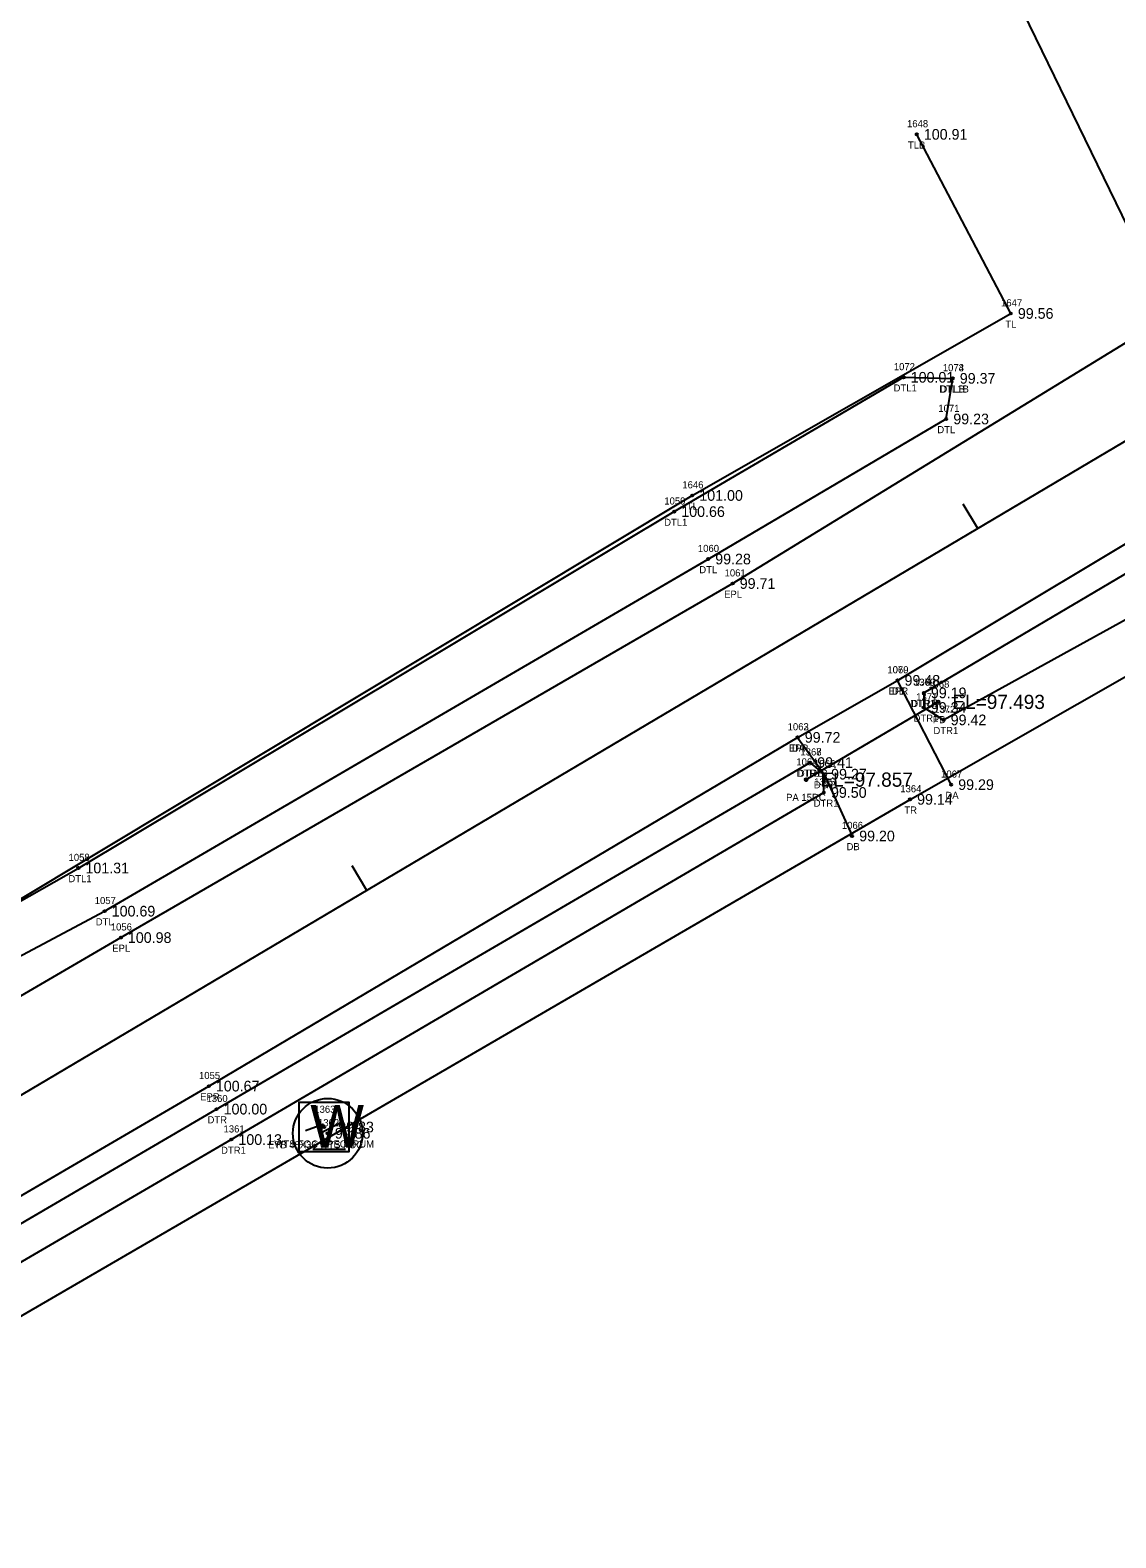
# Model space of a CAD drawing. Extents: x 2529517 to 2532038, y 935000 to 936944.
# Drawn here: x 2530596.5 to 2530749.4, y 935585.6 to 935798 of the extents above; entities that cross this region are included whole.
import ezdxf

# ---------------------------------------------------------------- set-up
doc = ezdxf.new("R2010")
doc.units = 0
for name, color, linetype in [('Default', 7, 'Continuous'), ('RD_EX_Bldg', 7, 'Continuous'), ('RD_EX_DR_Pipe', 7, 'Continuous'), ('RD_EX_DR_Pipe_txCode', 7, 'Continuous'), ('RD_EX_Driveway', 7, 'Continuous'), ('RD_EX_Driveway_txCode', 7, 'Continuous'), ('RD_EX_H2O', 7, 'Continuous'), ('RD_EX_H2O_txCode', 7, 'Continuous'), ('RD_EX_Road', 7, 'Continuous'), ('RD_EX_Road_txCode', 7, 'Continuous'), ('RD_EX_TX_Driveway_ELEV', 7, 'Continuous'), ('RD_EX_TX_H2O_ELEV', 7, 'Continuous'), ('RD_EX_TX_Road_ELEV', 7, 'Continuous'), ('RD_EX_TX_UT_ELEV', 7, 'Continuous'), ('RD_EX_TX_VEG_ELEV', 7, 'Continuous'), ('RD_EX_UT', 7, 'Continuous'), ('RD_EX_UT_txCode', 7, 'Continuous'), ('RD_EX_VEG', 7, 'Continuous'), ('RD_EX_VEG_txCode', 7, 'Continuous'), ('RD_HC_Cl', 7, 'Continuous'), ('RD_HC_Data_Tic', 7, 'Continuous'), ('RD_SMD_Locator', 7, 'Continuous'), ('RD_TX_Pipe_ElevEX', 7, 'Continuous')]:
    doc.layers.add(name, color=color, linetype=linetype)

msp = doc.modelspace()

# ---------------------------------------------------------------- linework, layer by layer
at = {"layer": 'Default'}
msp.add_line((2530557.05, 935625.34), (2531768.07, 936342.55), dxfattribs=at)
at = {"layer": 'RD_EX_Bldg'}
msp.add_lwpolyline([(2530713.74, 935846.97), (2530751.17, 935770.08), (2530778.04, 935782.8), (2530741.92, 935860.25), (2530713.74, 935846.97)], dxfattribs=at)
at = {"layer": 'RD_EX_DR_Pipe'}
msp.add_line((2530705.83, 935692.4), (2530724.42, 935703.35), dxfattribs=at)
at = {"layer": 'RD_EX_Driveway'}
msp.add_line((2530726.23, 935691.69), (2530718.67, 935706.38), dxfattribs=at)
msp.add_lwpolyline([(2530704.62, 935698.35), (2530708.33, 935693.17), (2530712.28, 935684.46)], dxfattribs=at)
at = {"layer": 'RD_EX_H2O'}
for points in [[(2530722.38, 935704.62), (2530796.68, 935748.53), (2530872.47, 935794.26), (2530874.44, 935791.96), (2530875.06, 935785.48)], [(2530722.38, 935704.62), (2530722.37, 935702.56), (2530725.17, 935700.81), (2530799.94, 935742.04), (2530875.06, 935785.48)], [(2530543.2, 935642.77), (2530561.27, 935656.09), (2530603.32, 935679.95), (2530687.23, 935730.15), (2530719.54, 935749.07), (2530726.45, 935748.92)], [(2530543.2, 935642.77), (2530564.55, 935651.29), (2530607.02, 935673.87), (2530692.01, 935723.47), (2530725.54, 935743.2), (2530726.45, 935748.92)], [(2530585.61, 935271.89), (2530554.63, 935366.84), (2530523, 935462.44), (2530497.71, 935534.53), (2530497.63, 935550.35), (2530501.9, 935567.07), (2530512.76, 935580.06), (2530532.29, 935593.54), (2530580.75, 935621.41), (2530622.78, 935645.99), (2530706.38, 935694.8)], [(2530592.81, 935273.73), (2530561.2, 935369.39), (2530529.39, 935464.13), (2530504.24, 935535.46), (2530502.94, 935549.83), (2530506.75, 935563.82), (2530516.63, 935575.2), (2530535.16, 935588.8), (2530583.24, 935617.5), (2530624.86, 935641.7), (2530708.31, 935690.59), (2530708.33, 935693.17), (2530706.38, 935694.8)]]:
    msp.add_lwpolyline(points, dxfattribs=at)
at = {"layer": 'RD_EX_Road'}
for points in [[(2530213.13, 935600.16), (2530313.8, 935600.81), (2530414.15, 935601.13), (2530426.72, 935601.43), (2530429.46, 935603.55), (2530467.67, 935608.62), (2530486.46, 935612.38), (2530518.02, 935622.55), (2530522.16, 935623.68), (2530567.91, 935646.01), (2530609.3, 935670.15), (2530695.46, 935720.02), (2530775.85, 935769.27), (2530868.29, 935824.03), (2530924.84, 935856.95), (2530956.21, 935875.82), (2531040.72, 935926.38), (2531079.45, 935947.76)], [(2530212.44, 935579.72), (2530312.61, 935580.14), (2530402.98, 935580.64), (2530451.06, 935579.53), (2530466.91, 935580.35), (2530487.45, 935583.29), (2530533.43, 935598.45), (2530580.28, 935625.08), (2530621.69, 935649.23), (2530704.62, 935698.35), (2530718.67, 935706.38), (2530795.45, 935752.36), (2530871.33, 935796.67), (2530882.4, 935803.04), (2530947.17, 935842.26), (2530966, 935852.42), (2530992.72, 935868), (2531009.49, 935879.01), (2531052.39, 935904.85), (2531090.88, 935928.23)]]:
    msp.add_lwpolyline(points, dxfattribs=at)
at = {"layer": 'RD_EX_UT'}
msp.add_line((2530636.32, 935640.37), (2530640.94, 935640.37), dxfattribs=at)
msp.add_lwpolyline([(2530634.42, 935639.97), (2530634.42, 935646.97), (2530641.42, 935646.97), (2530641.42, 935639.97)], close=True, dxfattribs=at)
msp.add_lwpolyline([(2530635.32, 935642.96), (2530637.74, 935643.86), (2530637.39, 935642.61), (2530640.44, 935644.21)], dxfattribs=at)
msp.add_circle((2530638.44, 935642.58), 4.91, dxfattribs=at)
at = {"layer": 'RD_EX_VEG'}
for points in [[(2530509.61, 935783.22), (2530537.51, 935723.48), (2530546.27, 935646.2), (2530689.77, 935732.43), (2530734.63, 935758.06), (2530721.39, 935783.29)], [(2530523.95, 935565.79), (2530539.5, 935582.04), (2530586.22, 935611.61), (2530720.44, 935689.62), (2530802.59, 935736.49), (2530863.89, 935770.01)]]:
    msp.add_lwpolyline(points, dxfattribs=at)
at = {"layer": 'RD_HC_Cl'}
msp.add_line((2530557.05, 935625.34), (2531768.07, 936342.55), dxfattribs=at)
at = {"layer": 'RD_HC_Data_Tic'}
for p, q in [((2530729.98, 935727.76), (2530727.94, 935731.2)), ((2530643.94, 935676.8), (2530641.9, 935680.24))]:
    msp.add_line(p, q, dxfattribs=at)
at = {"layer": 'RD_SMD_Locator'}
for centre, radius in [((2530721.39, 935783.29), 0.15), ((2530734.63, 935758.06), 0.15), ((2530719.54, 935749.07), 0.15), ((2530726.45, 935748.92), 0.15), ((2530726.45, 935748.92), 0.15), ((2530725.54, 935743.2), 0.15), ((2530689.77, 935732.43), 0.15), ((2530687.23, 935730.15), 0.15), ((2530692.01, 935723.47), 0.15), ((2530695.46, 935720.02), 0.15), ((2530718.67, 935706.38), 0.15), ((2530718.67, 935706.38), 0.15), ((2530722.38, 935704.62), 0.15), ((2530722.38, 935704.62), 0.15), ((2530722.37, 935702.56), 0.15), ((2530724.42, 935703.35), 0.2), ((2530725.17, 935700.81), 0.15), ((2530704.62, 935698.35), 0.15), ((2530704.62, 935698.35), 0.15), ((2530706.38, 935694.8), 0.15), ((2530706.38, 935694.8), 0.15), ((2530708.33, 935693.17), 0.15), ((2530708.33, 935693.17), 0.15), ((2530705.83, 935692.4), 0.2), ((2530726.23, 935691.69), 0.15), ((2530708.31, 935690.59), 0.15), ((2530720.44, 935689.62), 0.15), ((2530712.28, 935684.46), 0.15), ((2530603.32, 935679.95), 0.15), ((2530607.02, 935673.87), 0.15), ((2530609.3, 935670.15), 0.15), ((2530621.69, 935649.23), 0.15), ((2530622.78, 935645.99), 0.15), ((2530637.92, 935643.47), 0.15), ((2530638.44, 935642.58), 0.15), ((2530624.86, 935641.7), 0.15)]:
    msp.add_circle(centre, radius, dxfattribs=at)

# ---------------------------------------------------------------- texts
at = {"layer": 'RD_EX_DR_Pipe_txCode'}
for s, p in [('1068', (2530723.01, 935705.35)), ('PB', (2530723.64, 935700.35)), ('1064', (2530704.43, 935694.4)), ('PA 15RC', (2530702.99, 935689.4))]:
    msp.add_text(s, height=1, dxfattribs=at).set_placement(p)
at = {"layer": 'RD_EX_Driveway_txCode'}
for s, p in [('1069', (2530717.26, 935707.38)), ('DB', (2530717.89, 935704.38)), ('1063', (2530703.21, 935699.35)), ('DA', (2530703.82, 935696.35)), ('1065', (2530706.92, 935694.17)), ('1067', (2530724.82, 935692.69)), ('D', (2530708.02, 935691.17)), ('DA', (2530725.43, 935689.69)), ('1066', (2530710.85, 935685.46)), ('DB', (2530711.5, 935682.46))]:
    msp.add_text(s, height=1, dxfattribs=at).set_placement(p)
at = {"layer": 'RD_EX_H2O_txCode'}
for s, p in [('1072', (2530718.16, 935750.07)), ('1073', (2530725.06, 935749.92)), ('1074', (2530725.06, 935749.92)), ('DTL1', (2530718.13, 935747.07)), ('DTL1B', (2530724.57, 935746.92)), ('DTLB', (2530724.73, 935746.92)), ('1071', (2530724.43, 935744.2)), ('DTL', (2530724.29, 935741.2)), ('1059', (2530685.84, 935731.15)), ('DTL1', (2530685.82, 935728.15)), ('1060', (2530690.57, 935724.47)), ('DTL', (2530690.77, 935721.47)), ('1370', (2530720.99, 935705.62)), ('1369', (2530721.01, 935705.62)), ('1371', (2530721.31, 935703.56)), ('DTR1A', (2530720.46, 935702.62)), ('DTRA', (2530720.62, 935702.62)), ('1372', (2530723.83, 935701.81)), ('DTR1', (2530720.94, 935700.56)), ('DTR1', (2530723.74, 935698.81)), ('1367', (2530705.01, 935695.8)), ('1368', (2530705.01, 935695.8)), ('DTR1B', (2530704.47, 935692.8)), ('DTRB', (2530704.64, 935692.8)), ('1366', (2530706.93, 935694.17)), ('DTR1', (2530706.89, 935691.17)), ('1365', (2530706.94, 935691.59)), ('DTR1', (2530706.88, 935688.59)), ('1058', (2530601.94, 935680.95)), ('DTL1', (2530601.92, 935677.95)), ('1057', (2530605.63, 935674.87)), ('DTL', (2530605.77, 935671.87)), ('1360', (2530621.37, 935646.99)), ('DTR', (2530621.51, 935643.99)), ('1361', (2530623.77, 935642.7)), ('DTR1', (2530623.42, 935639.7))]:
    msp.add_text(s, height=1, dxfattribs=at).set_placement(p)
at = {"layer": 'RD_EX_Road_txCode'}
for s, p in [('1061', (2530694.33, 935721.02)), ('EPL', (2530694.26, 935718.02)), ('1070', (2530717.24, 935707.38)), ('EPR', (2530717.44, 935704.38)), ('1062', (2530703.21, 935699.35)), ('EPR', (2530703.39, 935696.35)), ('1056', (2530607.89, 935671.15)), ('EPL', (2530608.09, 935668.15)), ('1055', (2530620.31, 935650.23)), ('EPR', (2530620.47, 935647.23))]:
    msp.add_text(s, height=1, dxfattribs=at).set_placement(p)
at = {"layer": 'RD_EX_TX_Driveway_ELEV'}
for s, p in [('99.48', (2530719.67, 935705.63)), ('99.72', (2530705.62, 935697.6)), ('99.27', (2530709.33, 935692.42)), ('99.29', (2530727.23, 935690.94)), ('99.20', (2530713.28, 935683.71))]:
    msp.add_text(s, height=1.5, dxfattribs=at).set_placement(p)
at = {"layer": 'RD_EX_TX_H2O_ELEV'}
for s, p in [('100.01', (2530720.54, 935748.32)), ('99.37', (2530727.45, 935748.17)), ('99.37', (2530727.45, 935748.17)), ('99.23', (2530726.54, 935742.45)), ('100.66', (2530688.23, 935729.4)), ('99.28', (2530693.01, 935722.72)), ('99.19', (2530723.38, 935703.87)), ('99.19', (2530723.38, 935703.87)), ('99.34', (2530723.37, 935701.81)), ('99.42', (2530726.17, 935700.06)), ('99.41', (2530707.38, 935694.05)), ('99.41', (2530707.38, 935694.05)), ('99.27', (2530709.33, 935692.42)), ('99.50', (2530709.31, 935689.84)), ('101.31', (2530604.32, 935679.2)), ('100.69', (2530608.02, 935673.12)), ('100.00', (2530623.78, 935645.24)), ('100.13', (2530625.86, 935640.95))]:
    msp.add_text(s, height=1.5, dxfattribs=at).set_placement(p)
at = {"layer": 'RD_EX_TX_Road_ELEV'}
for s, p in [('99.71', (2530696.46, 935719.27)), ('99.48', (2530719.67, 935705.63)), ('99.72', (2530705.62, 935697.6)), ('100.98', (2530610.3, 935669.4)), ('100.67', (2530622.69, 935648.48))]:
    msp.add_text(s, height=1.5, dxfattribs=at).set_placement(p)
at = {"layer": 'RD_EX_TX_UT_ELEV'}
for s, p in [('99.86', (2530639.44, 935641.83)), ('99.83', (2530639.92, 935642.72))]:
    msp.add_text(s, height=1.5, dxfattribs=at).set_placement(p)
at = {"layer": 'RD_EX_TX_VEG_ELEV'}
for s, p in [('100.91', (2530722.39, 935782.54)), ('99.56', (2530735.63, 935757.31)), ('101.00', (2530690.77, 935731.68)), ('99.14', (2530721.44, 935688.87))]:
    msp.add_text(s, height=1.5, dxfattribs=at).set_placement(p)
at = {"layer": 'RD_EX_UT'}
msp.add_text('W', height=6, dxfattribs=at).set_placement((2530635.98, 935640.58))
at = {"layer": 'RD_EX_UT_txCode'}
for s, p in [('1363', (2530636.55, 935645.47)), ('1362', (2530637.07, 935643.58)), ('ETB 48X36 WTS FOC', (2530630.05, 935640.47)), ('WTS FOC SPECTRUM', (2530630.92, 935640.58))]:
    msp.add_text(s, height=1, dxfattribs=at).set_placement(p)
at = {"layer": 'RD_EX_VEG_txCode'}
for s, p in [('1648', (2530720.02, 935784.29)), ('TLB', (2530720.15, 935781.29)), ('1647', (2530733.26, 935759.06)), ('TL', (2530733.86, 935756.06)), ('1646', (2530688.38, 935733.43)), ('TL', (2530689, 935730.43)), ('1364', (2530719.07, 935690.62)), ('TR', (2530719.64, 935687.62))]:
    msp.add_text(s, height=1, dxfattribs=at).set_placement(p)
at = {"layer": 'RD_TX_Pipe_ElevEX'}
for s, p in [('EL=97.493', (2530726.42, 935702.35)), ('EL=97.857', (2530707.83, 935691.4))]:
    msp.add_text(s, height=2, dxfattribs=at).set_placement(p)

doc.saveas('drawing.dxf')
